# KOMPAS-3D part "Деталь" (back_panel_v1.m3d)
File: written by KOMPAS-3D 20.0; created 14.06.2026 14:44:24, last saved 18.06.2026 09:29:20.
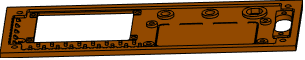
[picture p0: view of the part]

Document properties: Полное имя файла: D:\RicWork\Project-EPS32\box_compas\back_panel_v1.m3d

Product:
- Part/product: Деталь
    Материал: Фанера, береза,ФСФ ВВ/С ГОСТ 3916.1-2018 (density 760 kg/m3)
    Масса: 0.0255568

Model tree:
1. Эскиз:1
2. Элемент выдавливания:1
     Расстояние 1 = 4
3. Эскиз:2  (with: Элемент выдавливания:1)
4. Элемент выдавливания:2
     Расстояние 2 = 4
5. Массив по сетке:1  (with: Элемент выдавливания:2, Эскиз:2)  (4 pattern instances)
     Шаг 1 = 83; Угол раствора = 90; Шаг 2 = 36
6. Эскиз:3  (with: Элемент выдавливания:1)
7. Элемент выдавливания:3
     Расстояние 2 = 4
8. Эскиз:4  (with: Элемент выдавливания:1, Элемент выдавливания:2)
9. Эскиз:5  (with: Элемент выдавливания:1)
10. Элемент выдавливания:5
     Расстояние 2 = 2
11. Эскиз:6  (with: Элемент выдавливания:1, Элемент выдавливания:5)
12. Элемент выдавливания:6
     Расстояние 2 = 4
13. Скругление:2  (with: Элемент выдавливания:5)
     Радиус = 1.5
14. Скругление:3  (with: Элемент выдавливания:3)
     Радиус = 1.5
15. Эскиз:8  (with: Элемент выдавливания:1)
16. Элемент выдавливания:8
     Расстояние 2 = 4
17. Элемент выдавливания:9
     Расстояние 2 = 4
18. Скругление:4  (with: Элемент выдавливания:8)
     Радиус = 6
19. Эскиз:9  (with: Элемент выдавливания:1, Элемент выдавливания:3)
20. Элемент выдавливания:10
     Расстояние 2 = 4
21. Скругление:5  (with: Элемент выдавливания:10)
     Радиус = 1
22. Эскиз:10  (with: Элемент выдавливания:1, Элемент выдавливания:3, Элемент выдавливания:10, Скругление:5)
23. Элемент выдавливания:11
     Расстояние 2 = 2.5
24. Скругление:6  (with: Элемент выдавливания:11)
     Радиус = 1
25. Эскиз:11  (with: Элемент выдавливания:5)
26. Эскиз:12  (with: Элемент выдавливания:5)
27. Элемент выдавливания:13
     Расстояние 1 = 2
28. Элемент выдавливания:14
     Расстояние 2 = 4
29. Эскиз:13  (with: Элемент выдавливания:5, Элемент выдавливания:8, Элемент выдавливания:1, Скругление:4)
30. Элемент выдавливания:16
     Расстояние 1 = 2
31. Эскиз:14  (with: Элемент выдавливания:16, Элемент выдавливания:1)
32. Элемент выдавливания:17
     Расстояние 2 = 4
33. Эскиз:15  (with: Элемент выдавливания:5, Элемент выдавливания:14)
34. Эскиз:16  (with: Элемент выдавливания:1)
35. Элемент выдавливания:19
     Расстояние 2 = 4
36. Эскиз:17  (with: Элемент выдавливания:1, Элемент выдавливания:19)
37. Элемент выдавливания:23
     Расстояние 2 = 4
38. Массив по концентрической сетке:2  (with: Элемент выдавливания:23, Эскиз:17, Элемент выдавливания:19)  (6 pattern instances)
     Шаг 2 = 360
39. Эскиз:20  (with: Элемент выдавливания:5, Элемент выдавливания:19)
40. Элемент выдавливания:24
     Расстояние 2 = 1.5
41. Скругление:7  (with: Элемент выдавливания:24)
     Радиус = 3
42. Эскиз:22  (with: Элемент выдавливания:5)
43. Элемент выдавливания:26
     Расстояние 1 = 2
44. Скругление:8  (with: Элемент выдавливания:26)
     Радиус = 0.5
45. Массив по сетке:5  (with: Элемент выдавливания:26, Эскиз:22, Скругление:8, Элемент выдавливания:5)  (10 pattern instances)
     Шаг 1 = 5; Угол раствора = 90
46. Эскиз:24  (with: Элемент выдавливания:5, Скругление:2)
47. Элемент выдавливания:27
     Расстояние 1 = 2
48. Фаска:3  (with: Элемент выдавливания:27)
     Угол = 45; Длина 1 = 2; Длина 2 = 2
49. Массив по сетке:6  (with: Элемент выдавливания:27, Эскиз:24, Фаска:3, Элемент выдавливания:1)  (5 pattern instances)
     Шаг 1 = 10; Угол раствора = 90
50. Скругление:9  (with: Элемент выдавливания:16)
     Радиус = 1
51. Эскиз:25  (with: Элемент выдавливания:5)
52. Элемент выдавливания:28
     Расстояние 1 = 2
53. Скругление:10  (with: Элемент выдавливания:28)
     Радиус = 0.5
54. Массив по сетке:7  (with: Элемент выдавливания:28, Эскиз:25, Скругление:10)  (17 pattern instances)
     Шаг 1 = 5; Угол раствора = 90
55. Эскиз:26  (with: Элемент выдавливания:5, Элемент выдавливания:28)
56. Элемент выдавливания:29
     Расстояние 1 = 2
57. Массив по сетке:9  (with: Элемент выдавливания:29, Эскиз:26, Элемент выдавливания:1, Элемент выдавливания:10)  (9 pattern instances)
     Шаг 1 = 10; Угол раствора = 90; Шаг 2 = 5.2
58. Эскиз:27  (with: Элемент выдавливания:5, Элемент выдавливания:29, Элемент выдавливания:28)
59. Элемент выдавливания:30
     Расстояние 1 = 2
60. Массив по сетке:10  (with: Элемент выдавливания:30, Эскиз:27, Элемент выдавливания:10)  (8 pattern instances)
     Шаг 1 = 10; Угол раствора = 90
61. Эскиз:28  (with: Элемент выдавливания:1, Элемент выдавливания:2)
62. Элемент выдавливания:33
     Расстояние 2 = 4
63. Элемент выдавливания:35  (labels: Фанера, береза,ФСФ ВВ/С ГОСТ 3916.1-2018)
     Расстояние 1 = 2

Referenced files in D:\RicWork\Project-EPS32\box_compas\: Back_Panel_Сборка_v1.a3d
